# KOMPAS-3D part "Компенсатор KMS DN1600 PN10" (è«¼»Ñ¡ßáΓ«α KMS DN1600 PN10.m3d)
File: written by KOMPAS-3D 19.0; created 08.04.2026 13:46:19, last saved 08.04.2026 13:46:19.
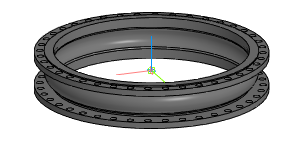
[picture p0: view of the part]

Document properties: Автор: Энергия; Полное имя файла: Z:\3.Личные\kachalov\3d для проектировщиков\7.1 Компенсатор\stp_Компенсатор KSM\Компенсатор KMS DN1600 PN10.m3d

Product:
- Part/product: Компенсатор KMS DN1600 PN10

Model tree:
1. Операция без истории:1  (labels: Компенсатор KMS DN1600 PN10)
